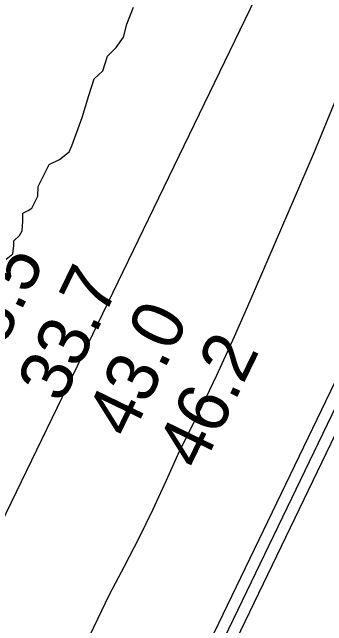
# Model space of a CAD drawing. Extents: x 3180038 to 3217926, y 922069 to 947485.
# Drawn here: x 3189778 to 3190185, y 936760 to 937552 of the extents above; entities that cross this region are included whole.
import ezdxf

# ---------------------------------------------------------------- set-up
doc = ezdxf.new("R2010")
doc.units = 0
for name, color, linetype in [('V-LEVE-TOET', 7, 'Continuous'), ('V-RIVR-EDGE', 7, 'Continuous'), ('V-RIVR-RANG', 7, 'Continuous'), ('V-ROAD-CNTR', 7, 'Continuous'), ('V-RRAP-FSHR', 7, 'Continuous'), ('V-TOPO-SHOR', 7, 'Continuous')]:
    doc.layers.add(name, color=color, linetype=linetype)

msp = doc.modelspace()

# ---------------------------------------------------------------- linework, layer by layer
at = {"layer": 'V-LEVE-TOET'}
msp.add_lwpolyline([(3189787.65, 936558.61), (3189903.67, 936800.25), (3189903.67, 936800.25), (3189923.05, 936836.66), (3189941.8, 936873.39), (3189959.93, 936910.43), (3189977.43, 936947.78), (3189994.15, 936985.08), (3189994.15, 936985.08), (3190018.75, 937034.12), (3190042.51, 937083.58), (3190065.41, 937133.45), (3190085.6, 937179.4), (3190085.6, 937179.4), (3190167.45, 937368.86), (3190167.45, 937368.86), (3190195.02, 937436.03), (3190223.74, 937502.7), (3190224.1, 937503.52), (3190224.1, 937503.52), (3190291.91, 937644.83)], dxfattribs=at)
at = {"layer": 'V-RIVR-EDGE'}
msp.add_lwpolyline([(3189770.06, 937233.36), (3189778.37, 937240.08), (3189779.96, 937250.97), (3189779.97, 937257.2), (3189787.25, 937263.92), (3189790.38, 937270.13), (3189791.44, 937282.58), (3189791.47, 937292.95), (3189798.22, 937296.05), (3189802.89, 937299.15), (3189810.71, 937314.69), (3189811.26, 937327.13), (3189816.99, 937338.53), (3189825.33, 937355.62), (3189838.84, 937362.33), (3189851.31, 937372.15), (3189854.96, 937379.92), (3189868.01, 937416.19), (3189876.9, 937444.7), (3189883.69, 937466.46), (3189895.13, 937476.81), (3189900.88, 937495.46), (3189912.32, 937506.84), (3189921.69, 937520.31), (3189925.88, 937536.89), (3189934.75, 937559.17)], dxfattribs=at)
at = {"layer": 'V-ROAD-CNTR'}
for points in [[(3191151.81, 939057.08), (3189829.73, 936317.66), (3189780.65, 936216.27), (3189729.57, 936116.68), (3189676.72, 936017.84), (3189622.44, 935919.01), (3189566.14, 935821.91), (3189508.34, 935726.16), (3189454.5, 935639.54), (3189409.28, 935567.56), (3189362.72, 935497.1), (3189314.86, 935427.34), (3189265.96, 935357.7), (3189215.67, 935289.53), (3189180.73, 935243.5), (3188970.65, 934976.35)], [(3191165.02, 939049.95), (3189843.24, 936311.14)], [(3191178.24, 939042.82), (3189856.74, 936304.61)]]:
    msp.add_lwpolyline(points, dxfattribs=at)
at = {"layer": 'V-RRAP-FSHR'}
msp.add_spline([(3188909.67, 936835.56), (3188947.17, 936904.9), (3189148.2, 937330.34), (3189156.65, 937362.67), (3189315.07, 937655.25), (3189456.11, 937980.67), (3189785.8, 938633.8), (3189989.58, 939082.49), (3190086.54, 939246.28), (3190202.2, 939544.14), (3190260.41, 939640.92), (3190317.47, 939690.4), (3190371.63, 939771.98), (3190383.24, 939818.37), (3190378.32, 939877.04), (3190456.71, 940024.39), (3190526.89, 940196.44), (3190631.99, 940397.77), (3190706.57, 940575.74), (3190844.1, 940852.1), (3190870.74, 940905.55), (3190891.62, 940984.86), (3190926.08, 941035.42), (3191101.29, 941369.43), (3191117.19, 941389.32)], degree=3, dxfattribs=at)
at = {"layer": 'V-TOPO-SHOR'}
msp.add_lwpolyline([(3189493.71, 936331.18), (3189730.17, 936824.36), (3190125.39, 937638.44), (3190165.92, 937722.89), (3190463.18, 938384.97), (3190601.68, 938648.45), (3190750.31, 938965.98), (3190804.36, 938901.8), (3190814.49, 938878.15), (3190817.87, 938837.62), (3190780.71, 938773.44), (3190743.55, 938702.5), (3190730.04, 938672.1), (3190723.29, 938641.7), (3190719.91, 938607.92), (3190713.15, 938577.51), (3190709.77, 938533.6), (3190709.77, 938496.44), (3190692.88, 938439.02), (3190675.99, 938364.7)], dxfattribs=at)

# ---------------------------------------------------------------- texts
at = {"layer": 'V-RIVR-RANG'}
for s, p in [('8.5', (3189766.3, 937118.89)), ('33.7', (3189841.82, 937045.52)), ('43.0', (3189930.61, 936999.43)), ('46.2', (3190021.93, 936958.56))]:
    msp.add_text(s, height=67, rotation=64.08833, dxfattribs=at).set_placement(p)

doc.saveas('drawing.dxf')
